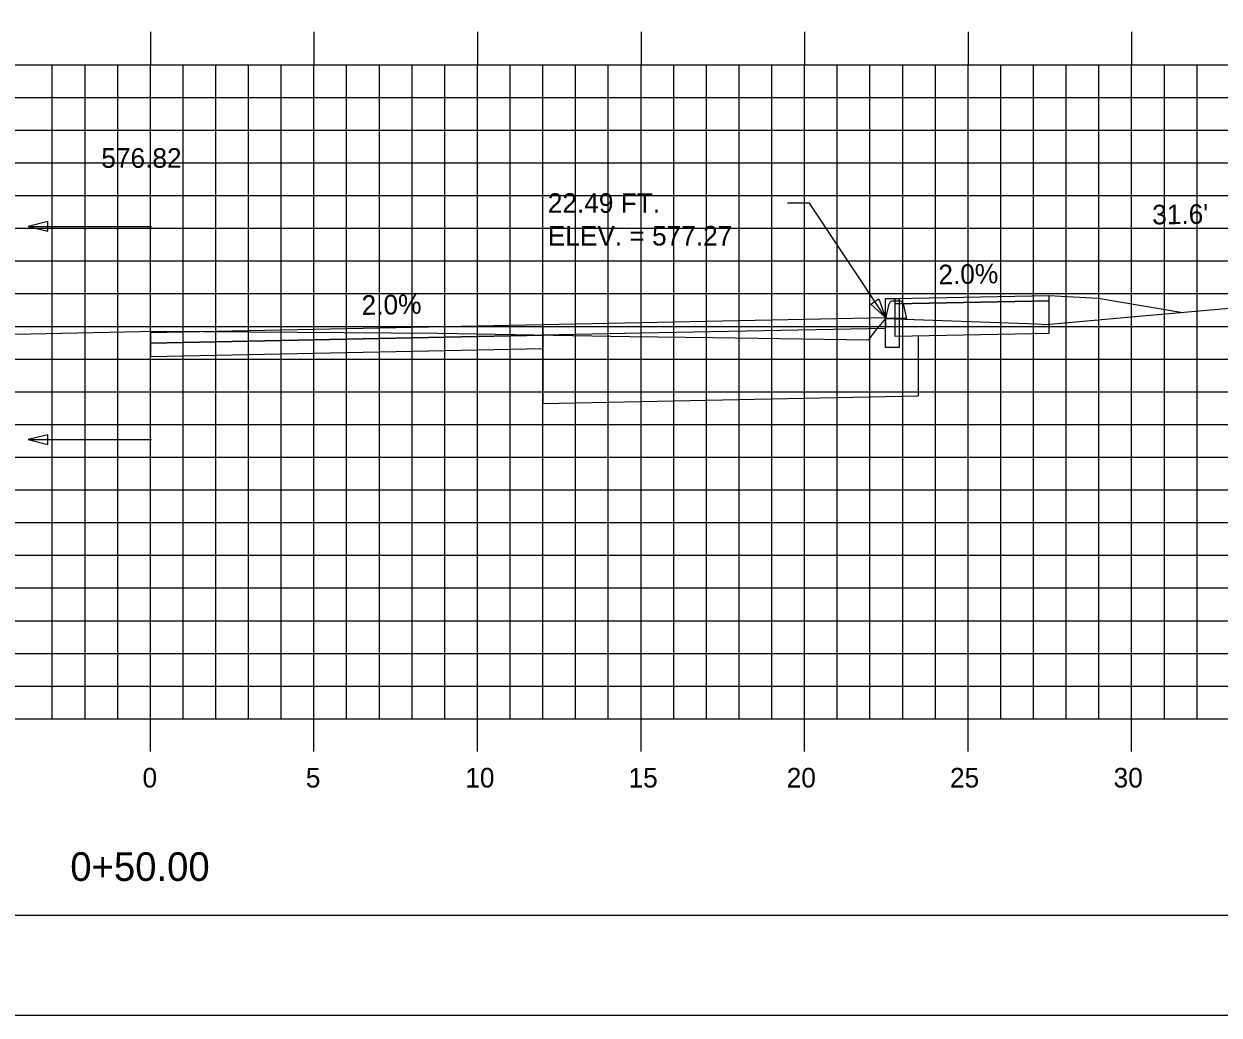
# Model space of a CAD drawing. Extents: x 1048343 to 1048513, y 781387 to 781497.
# Drawn here: x 1048422.25 to 1048458.79, y 781387.32 to 781417.62 of the extents above; entities that cross this region are included whole.
import ezdxf

# ---------------------------------------------------------------- set-up
doc = ezdxf.new("R2010")
doc.units = 0
for name, color, linetype in [('ANNOTATION', 7, 'Continuous'), ('BORDER', 7, 'Continuous'), ('D_Curb_Type1_Lt', 7, 'Continuous'), ('D_Roadway_Berm', 7, 'Continuous'), ('D_Roadway_Centerline', 7, 'Continuous'), ('D_Roadway_Centerline_Text', 7, 'Continuous'), ('D_Roadway_Edge_Shoulder', 7, 'Continuous'), ('D_Roadway_Edge_TW', 7, 'Continuous'), ('D_Roadway_Pavement', 7, 'Continuous'), ('D_Roadway_Sidewalks_Paved', 7, 'Continuous'), ('D_Roadway_SlopeLines', 7, 'Continuous'), ('D_Roadway_SubGrade', 7, 'Continuous'), ('D_Text_Standard', 7, 'Continuous'), ('H_V ANNOTATION', 7, 'Continuous'), ('MAJOR', 7, 'Continuous'), ('MINOR', 7, 'Continuous'), ('PLOT BOUNDARY', 7, 'Continuous'), ('S_Curb_Type_3', 7, 'Continuous'), ('S_Roadway_Centerline', 7, 'Continuous')]:
    doc.layers.add(name, color=color, linetype=linetype)

msp = doc.modelspace()

# ---------------------------------------------------------------- linework, layer by layer
at = {"layer": 'ANNOTATION'}
for p, q in [((1048422.382, 781411.431), (1048426.157, 781411.431)), ((1048422.382, 781404.913), (1048426.157, 781404.913))]:
    msp.add_line(p, q, dxfattribs=at)
for points in [[(1048422.982, 781411.581), (1048422.382, 781411.431), (1048422.982, 781411.281)], [(1048422.982, 781405.063), (1048422.382, 781404.913), (1048422.982, 781404.763)]]:
    msp.add_lwpolyline(points, close=True, dxfattribs=at)
at = {"layer": 'BORDER'}
msp.add_lwpolyline([(1048351.12, 781390.375), (1048511.12, 781390.375), (1048511.12, 781495.375), (1048351.12, 781495.375)], close=True, dxfattribs=at)
at = {"layer": 'D_Curb_Type1_Lt'}
msp.add_lwpolyline([(1048449.008, 781409.229), (1048449.008, 781407.729), (1048448.592, 781407.729), (1048448.592, 781409.229)], close=True, dxfattribs=at)
at = {"layer": 'D_Roadway_Berm'}
msp.add_lwpolyline([(1048453.592, 781409.323), (1048455.092, 781409.233)], dxfattribs=at)
at = {"layer": 'D_Roadway_Centerline'}
for p, q in [((1048426.119, 781404.913), (1048426.119, 781411.47)), ((1048426.119, 781408.191), (1048426.119, 781407.441))]:
    msp.add_line(p, q, dxfattribs=at)
at = {"layer": 'D_Roadway_Edge_Shoulder'}
msp.add_lwpolyline([(1048438.119, 781408.434), (1048441.119, 781408.495), (1048448.591, 781408.646), (1048448.591, 781408.313), (1048441.119, 781408.162), (1048438.119, 781408.101)], close=True, dxfattribs=at)
at = {"layer": 'D_Roadway_Edge_TW'}
msp.add_lwpolyline([(1048426.119, 781408.191), (1048438.119, 781408.434), (1048438.119, 781408.101), (1048426.119, 781407.858)], dxfattribs=at)
at = {"layer": 'D_Roadway_Pavement'}
msp.add_lwpolyline([(1048426.119, 781407.858), (1048438.119, 781408.101), (1048438.119, 781407.684), (1048426.119, 781407.441)], dxfattribs=at)
at = {"layer": 'D_Roadway_Sidewalks_Paved'}
msp.add_lwpolyline([(1048448.892, 781409.229), (1048453.592, 781409.323), (1048453.592, 781409.157), (1048448.892, 781409.063)], close=True, dxfattribs=at)
at = {"layer": 'D_Roadway_SlopeLines'}
msp.add_lwpolyline([(1048455.092, 781409.233), (1048457.68, 781408.802)], dxfattribs=at)
at = {"layer": 'D_Roadway_SubGrade'}
msp.add_line((1048438.119, 781408.101), (1048438.119, 781406.018), dxfattribs=at)
msp.add_lwpolyline([(1048448.892, 781409.063), (1048453.592, 781409.157), (1048453.592, 781408.157), (1048448.892, 781408.063)], close=True, dxfattribs=at)
for points in [[(1048438.119, 781408.101), (1048438.119, 781406.018), (1048449.591, 781406.25)], [(1048449.591, 781408.077), (1048449.591, 781406.25)]]:
    msp.add_lwpolyline(points, dxfattribs=at)
at = {"layer": 'D_Text_Standard'}
msp.add_lwpolyline([(1048448.591, 781408.646), (1048446.273, 781412.146), (1048445.593, 781412.146)], dxfattribs=at)
msp.add_lwpolyline([(1048448.591, 781408.646), (1048448.148, 781409.051), (1048448.391, 781409.212)], close=True, dxfattribs=at)
at = {"layer": 'MAJOR'}
for p, q in [((1048426.119, 781417.377), (1048426.119, 781416.375)), ((1048431.119, 781417.377), (1048431.119, 781416.375)), ((1048436.119, 781417.377), (1048436.119, 781416.375)), ((1048441.119, 781417.377), (1048441.119, 781416.375)), ((1048446.119, 781417.377), (1048446.119, 781416.375)), ((1048451.119, 781417.377), (1048451.119, 781416.375)), ((1048456.119, 781417.377), (1048456.119, 781416.375)), ((1048356.119, 781416.375), (1048496.119, 781416.375)), ((1048356.119, 781416.375), (1048496.119, 781416.375)), ((1048426.119, 781396.375), (1048426.119, 781416.375)), ((1048431.119, 781396.375), (1048431.119, 781416.375)), ((1048436.119, 781396.375), (1048436.119, 781416.375)), ((1048441.119, 781396.375), (1048441.119, 781416.375)), ((1048446.119, 781396.375), (1048446.119, 781416.375)), ((1048451.119, 781396.375), (1048451.119, 781416.375)), ((1048456.119, 781396.375), (1048456.119, 781416.375)), ((1048356.119, 781411.375), (1048496.119, 781411.375)), ((1048356.119, 781406.375), (1048496.119, 781406.375)), ((1048356.119, 781401.375), (1048496.119, 781401.375)), ((1048356.119, 781396.375), (1048496.119, 781396.375)), ((1048356.119, 781396.375), (1048496.119, 781396.375)), ((1048426.119, 781395.373), (1048426.119, 781396.375)), ((1048431.119, 781395.373), (1048431.119, 781396.375)), ((1048436.119, 781395.373), (1048436.119, 781396.375)), ((1048441.119, 781395.373), (1048441.119, 781396.375)), ((1048446.119, 781395.373), (1048446.119, 781396.375)), ((1048451.119, 781395.373), (1048451.119, 781396.375)), ((1048456.119, 781395.373), (1048456.119, 781396.375))]:
    msp.add_line(p, q, dxfattribs=at)
at = {"layer": 'MINOR'}
for p, q in [((1048423.119, 781396.375), (1048423.119, 781416.375)), ((1048424.119, 781396.375), (1048424.119, 781416.375)), ((1048425.119, 781396.375), (1048425.119, 781416.375)), ((1048427.119, 781396.375), (1048427.119, 781416.375)), ((1048428.119, 781396.375), (1048428.119, 781416.375)), ((1048429.119, 781396.375), (1048429.119, 781416.375)), ((1048430.119, 781396.375), (1048430.119, 781416.375)), ((1048432.119, 781396.375), (1048432.119, 781416.375)), ((1048433.119, 781396.375), (1048433.119, 781416.375)), ((1048434.119, 781396.375), (1048434.119, 781416.375)), ((1048435.119, 781396.375), (1048435.119, 781416.375)), ((1048437.119, 781396.375), (1048437.119, 781416.375)), ((1048438.119, 781396.375), (1048438.119, 781416.375)), ((1048439.119, 781396.375), (1048439.119, 781416.375)), ((1048440.119, 781396.375), (1048440.119, 781416.375)), ((1048442.119, 781396.375), (1048442.119, 781416.375)), ((1048443.119, 781396.375), (1048443.119, 781416.375)), ((1048444.119, 781396.375), (1048444.119, 781416.375)), ((1048445.119, 781396.375), (1048445.119, 781416.375)), ((1048447.119, 781396.375), (1048447.119, 781416.375)), ((1048448.119, 781396.375), (1048448.119, 781416.375)), ((1048449.119, 781396.375), (1048449.119, 781416.375)), ((1048450.119, 781396.375), (1048450.119, 781416.375)), ((1048452.119, 781396.375), (1048452.119, 781416.375)), ((1048453.119, 781396.375), (1048453.119, 781416.375)), ((1048454.119, 781396.375), (1048454.119, 781416.375)), ((1048455.119, 781396.375), (1048455.119, 781416.375)), ((1048457.119, 781396.375), (1048457.119, 781416.375)), ((1048458.119, 781396.375), (1048458.119, 781416.375)), ((1048356.119, 781415.375), (1048496.119, 781415.375)), ((1048356.119, 781414.375), (1048496.119, 781414.375)), ((1048356.119, 781413.375), (1048496.119, 781413.375)), ((1048356.119, 781412.375), (1048496.119, 781412.375)), ((1048356.119, 781410.375), (1048496.119, 781410.375)), ((1048356.119, 781409.375), (1048496.119, 781409.375)), ((1048356.119, 781408.375), (1048496.119, 781408.375)), ((1048356.119, 781407.375), (1048496.119, 781407.375)), ((1048356.119, 781405.375), (1048496.119, 781405.375)), ((1048356.119, 781404.375), (1048496.119, 781404.375)), ((1048356.119, 781403.375), (1048496.119, 781403.375)), ((1048356.119, 781402.375), (1048496.119, 781402.375)), ((1048356.119, 781400.375), (1048496.119, 781400.375)), ((1048356.119, 781399.375), (1048496.119, 781399.375)), ((1048356.119, 781398.375), (1048496.119, 781398.375)), ((1048356.119, 781397.375), (1048496.119, 781397.375))]:
    msp.add_line(p, q, dxfattribs=at)
at = {"layer": 'PLOT BOUNDARY'}
msp.add_lwpolyline([(1048343.026, 781387.316), (1048513.026, 781387.316), (1048513.026, 781497.316), (1048343.026, 781497.316)], close=True, dxfattribs=at)
at = {"layer": 'S_Curb_Type_3'}
for points in [[(1048448.831, 781409.157), (1048449.007, 781409.157)], [(1048449.129, 781409.06), (1048449.231, 781408.615), (1048448.606, 781408.615), (1048448.709, 781409.06)]]:
    msp.add_lwpolyline(points, dxfattribs=at)
for centre, start, end in [((1048448.831, 781409.032), 90, 167.0054), ((1048449.007, 781409.032), 12.9946, 90)]:
    msp.add_arc(centre, 0.125, start, end, dxfattribs=at)
at = {"layer": 'S_Roadway_Centerline'}
msp.add_lwpolyline([(1048399.613, 781407.977), (1048402.647, 781407.956), (1048411.34, 781407.93), (1048411.383, 781407.938), (1048413.295, 781407.949), (1048413.31, 781407.951), (1048426.292, 781408.232), (1048434.905, 781408.164), (1048440.786, 781408.065), (1048443.314, 781408.033), (1048448.081, 781407.963), (1048448.249, 781408.188), (1048448.606, 781408.615), (1048453.217, 781408.447), (1048453.503, 781408.435), (1048456.104, 781408.663), (1048463.623, 781409.324), (1048469.353, 781409.735), (1048471.95, 781409.995), (1048473.076, 781410.039), (1048489.208, 781410.246), (1048494.663, 781410.314), (1048496.119, 781410.415)], dxfattribs=at)

# ---------------------------------------------------------------- texts
at = {"layer": 'ANNOTATION'}
for s, rotation, p in [("31.6'", 0.7396, (1048456.751, 781411.49)), ('2.0%', 1.1458, (1048450.217, 781409.656)), ('2.0%', 1.1593, (1048432.583, 781408.722))]:
    msp.add_text(s, height=0.6, rotation=rotation, dxfattribs=at).set_placement(p)
at = {"layer": 'D_Roadway_Centerline'}
for s, p in [('C', (1048426.114, 781408.191)), ('L', (1048426.119, 781408.184))]:
    msp.add_text(s, height=0.0146, dxfattribs=at).set_placement(p)
at = {"layer": 'D_Roadway_Centerline_Text'}
msp.add_text('576.82', height=0.6, dxfattribs=at).set_placement((1048424.618, 781413.223))
at = {"layer": 'D_Text_Standard'}
for s, p in [('22.49 FT.', (1048438.268, 781411.846)), ('ELEV. = 577.27', (1048438.268, 781410.846))]:
    msp.add_text(s, height=0.6, dxfattribs=at).set_placement(p)
at = {"layer": 'H_V ANNOTATION'}
for s, height, p in [('0', 0.6, (1048425.878, 781394.275)), ('5', 0.6, (1048430.87, 781394.275)), ('10', 0.6, (1048435.745, 781394.275)), ('15', 0.6, (1048440.737, 781394.275)), ('20', 0.6, (1048445.573, 781394.275)), ('25', 0.6, (1048450.565, 781394.275)), ('30', 0.6, (1048455.568, 781394.275)), ('0+50.00', 0.875, (1048423.669, 781391.419))]:
    msp.add_text(s, height=height, dxfattribs=at).set_placement(p)
at = {"layer": 'S_Roadway_Centerline'}
for s, p in [('C', (1048426.287, 781408.232)), ('L', (1048426.292, 781408.225))]:
    msp.add_text(s, height=0.0146, dxfattribs=at).set_placement(p)

doc.saveas('drawing.dxf')
